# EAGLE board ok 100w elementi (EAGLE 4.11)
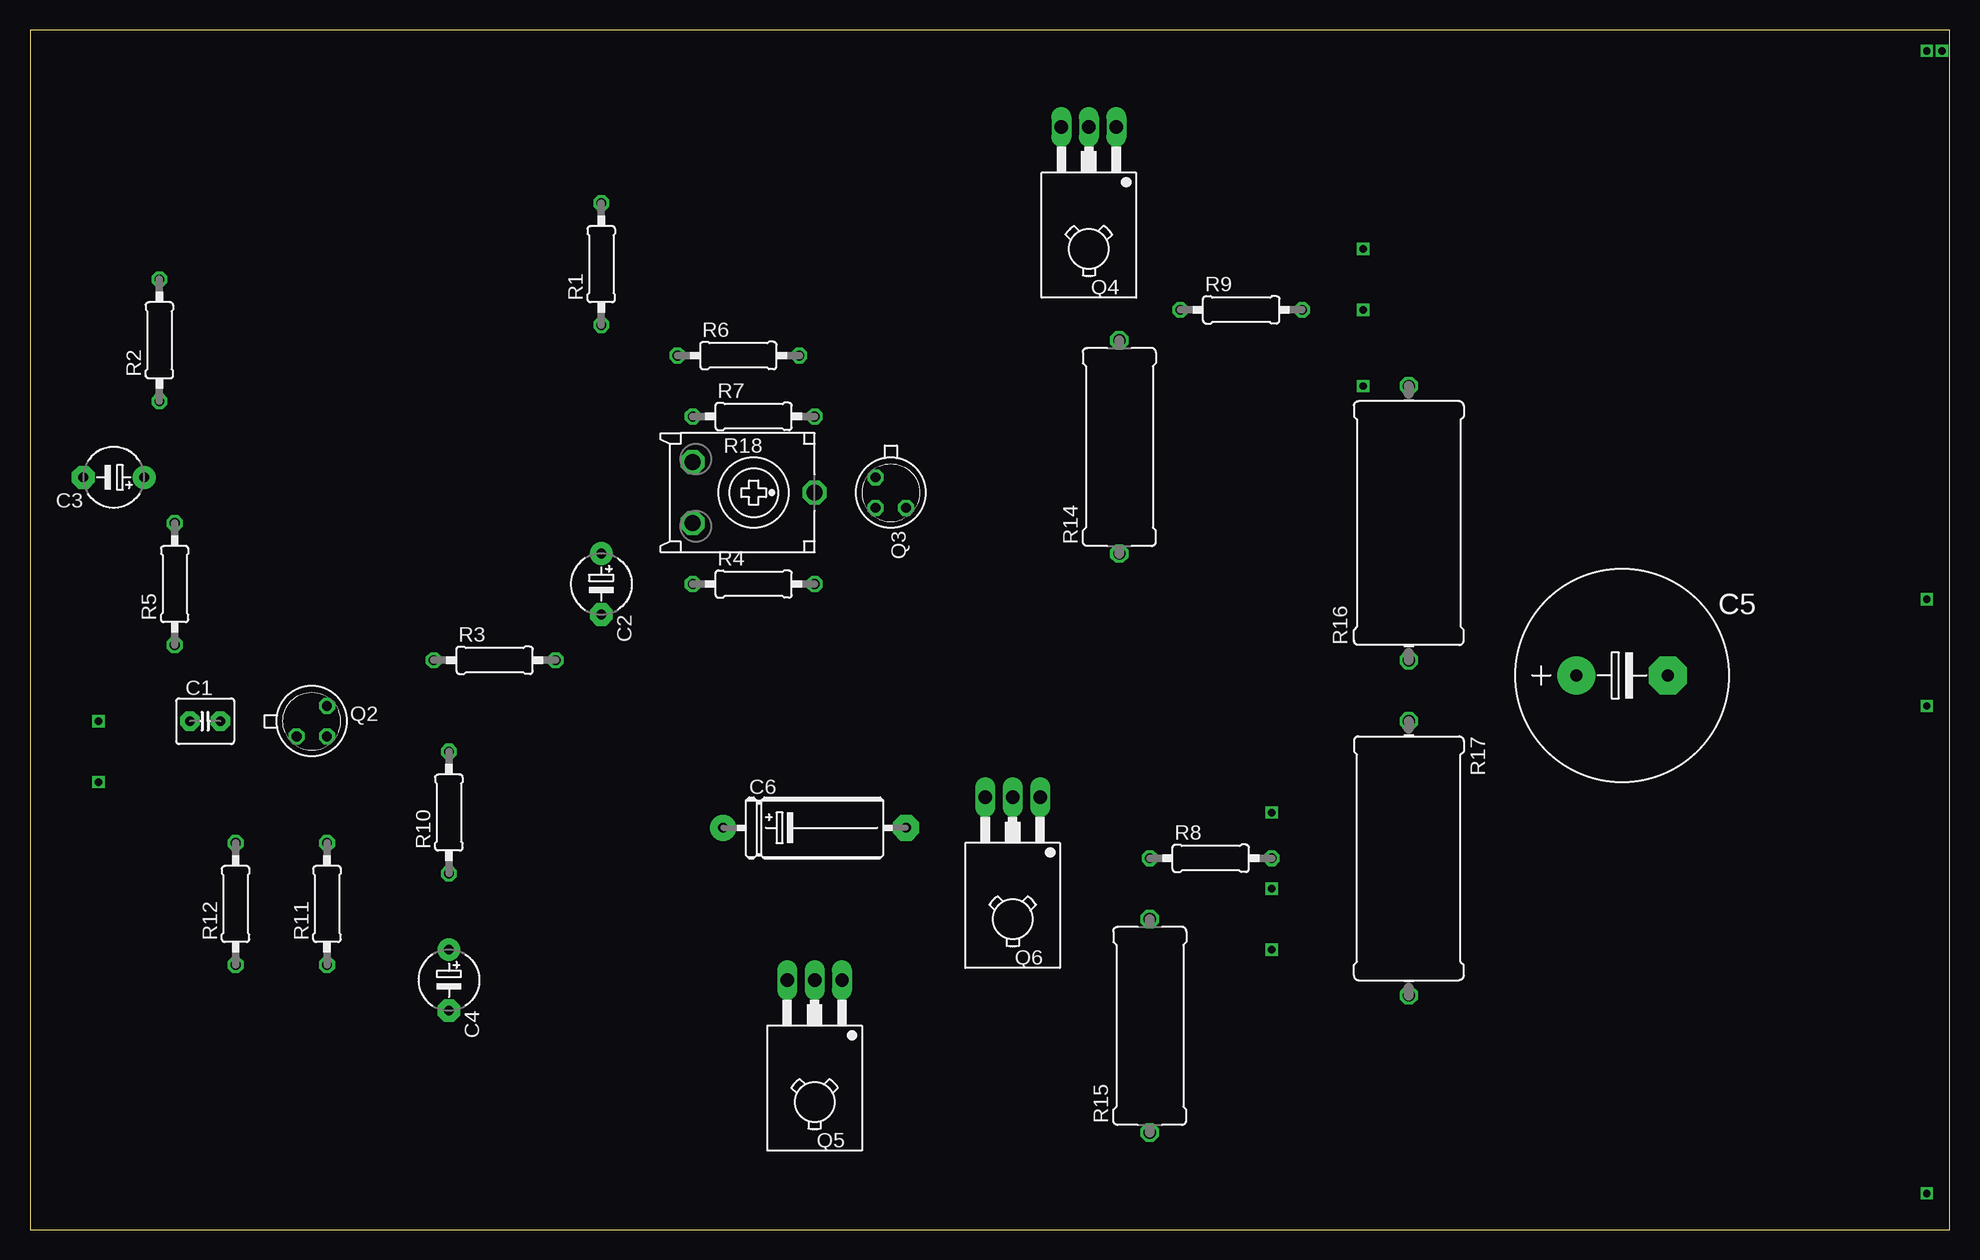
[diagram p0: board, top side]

Size 160 x 100 mm. Coordinates in mm from the lower left corner, seen from the top.
Outline: 0,0 160,0 160,100 0,100 0,0
Copper layers (1*16): Top 0.035mm / dielectric 1.5mm / Bottom 0.035mm
Design rules "default": minimum track width 10mil, minimum drill 24mil, track to track 8mil, track to pad 8mil, pad to pad 8mil, via to via 8mil, smd to smd 8mil, copper to edge 40mil, drill to drill 8mil, minimum pad ring 10mil, minimum via ring 8mil, stop-mask expansion 4mil, vias tented up to drill 0mil, thermal gap 10mil

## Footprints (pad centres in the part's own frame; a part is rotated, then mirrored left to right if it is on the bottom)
C2.5-4 = drill 0.813 pad 1.6 octagon: 1 -1.27,0; 2 1.27,0
E5-5 = drill 0.813 pad 1.905 round: + -2.54,0 | drill 0.813 pad 1.905 octagon: - 2.54,0
E7,5-18 = drill 1.016 pad 3.15 round: + -3.81,0 | drill 1.016 pad 3.15 octagon: - 3.81,0
E15-5 = drill 0.813 pad 2.159 round: + -7.62,0 | drill 0.813 pad 2.159 octagon: - 7.62,0
TO18 = drill 0.813 octagon: 1 -1.27,-1.27; 2 1.27,-1.27; 3 1.27,1.27
TO126 = drill 1.118 long: 1 -2.286,-5.08; 2 0,-5.08; 3 2.286,-5.08 | hole 3.302: 0,5.08
0207/10 = drill 0.813 octagon: 1 -5.08,0; 2 5.08,0
0617/17 = drill 1.016 octagon: 1 -8.89,0; 2 8.89,0
0922/22 = drill 1.016 octagon: 1 -11.43,0; 2 11.43,0
ECP10S = drill 1.321 octagon: A -2.54,-5.08; E 2.54,-5.08; S 0,5.08

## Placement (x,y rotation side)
C1  470nF  [C2.5-4]  14.6,42.38 0 top
C2  100uF  [E5-5]  47.62,53.81 270 top
C3  22uF ili 47uF  [E5-5]  6.98,62.7 180 top
C4  100uF  [E5-5]  34.92,20.79 270 top
C5  3300uF  [E7,5-18]  132.71,46.19 0 top
C6  150pF  [E15-5]  65.4,33.49 0 top
Q2  BC177  [TO18]  23.49,42.38 0 top
Q3  BC107  [TO18]  71.75,61.43 270 top
Q4  BD139  [TO126]  88.26,86.83 180 top
Q5  BD139  [TO126]  65.4,15.71 180 top
Q6  BD140  [TO126]  81.91,30.95 180 top
R1  1K5  [0207/10]  47.62,80.48 90 top
R2  56K  [0207/10]  10.79,74.13 90 top
R3  2K  [0207/10]  38.73,47.46 0 top
R4  470  [0207/10]  60.32,53.81 0 top
R5  470K  [0207/10]  12.06,53.81 90 top
R6  1K5  [0207/10]  59.05,72.86 0 top
R7  470  [0207/10]  60.32,67.78 0 top
R8  10  [0207/10]  98.42,30.95 0 top
R9  10  [0207/10]  100.96,76.67 0 top
R10  100  [0207/10]  34.92,34.76 90 top
R11  1K  [0207/10]  24.76,27.14 90 top
R12  330K  [0207/10]  17.14,27.14 90 top
R14  100 2w  [0617/17]  90.8,65.24 90 top
R15  100 2w  [0617/17]  93.34,16.98 90 top
R16  0R39  [0922/22]  114.93,58.89 90 top
R17  0R39  [0922/22]  114.93,30.95 270 top
R18  500  [ECP10S]  60.32,61.43 270 top

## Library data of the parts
C1 = capacitor-wima
C2-C6 R1-R12 R14-R17 = rcl
Q2 Q6 = transistor-pnp
Q3-Q5 = transistor-npn
R18 = pot

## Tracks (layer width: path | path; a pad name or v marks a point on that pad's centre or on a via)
N$1  (via drill 0.61)
  other vias: 103.5,28.41
N$2  (via drill 0.61)
  other vias: 103.5,34.76
N$3  (via drill 0.61)
  other vias: 103.5,23.33
N$4  (via drill 0.61)
  other vias: 158.11,43.65
N$5  (via drill 0.61)
  other vias: 158.11,52.54
N$6  (via drill 0.61)
  other vias: 111.12,76.67
N$7  (via drill 0.61)
  other vias: 111.12,70.32
N$8  (via drill 0.61)
  other vias: 111.12,81.75
N$9  (via drill 0.61)
  other vias: 5.71,37.3
N$10  (via drill 0.61)
  other vias: 158.11,98.26
N$11  (via drill 0.61)
  other vias: 158.11,3.01
N$12  (via drill 0.61)
  other vias: 159.38,98.26
N$13  (via drill 0.61)
  other vias: 5.71,42.38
